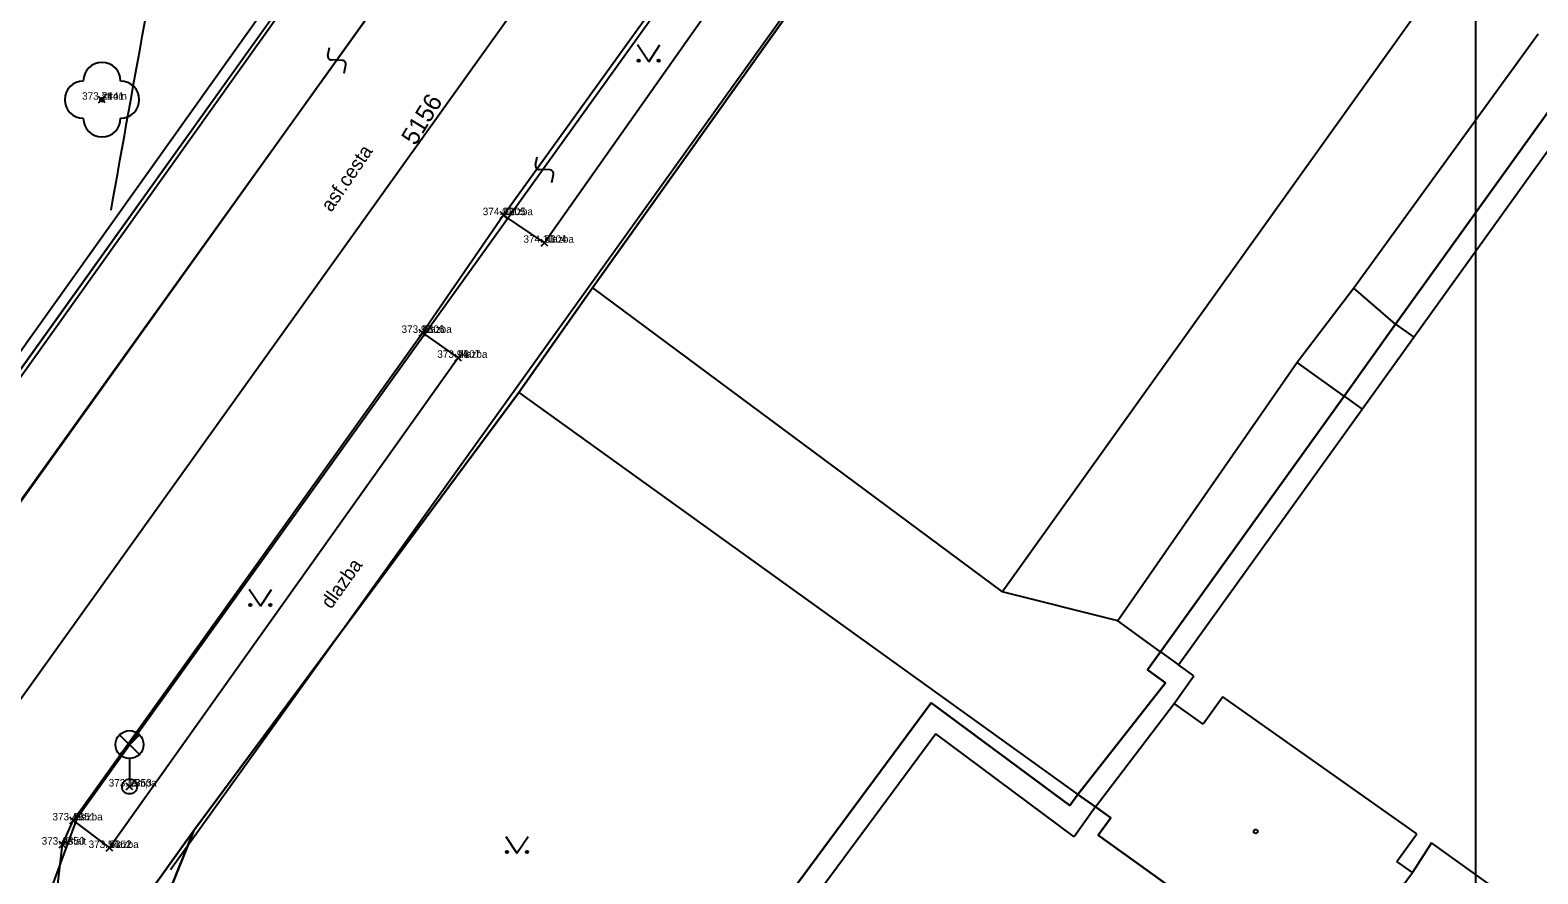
# Model space of a CAD drawing. Extents: x -400488 to -400124, y -1251493 to -1251223.
# Drawn here: x -400289.23 to -400248.76, y -1251399.85 to -1251377.2 of the extents above; entities that cross this region are included whole.
import ezdxf

# ---------------------------------------------------------------- set-up
doc = ezdxf.new("R2010")
doc.units = 0
for name, color, linetype in [('Level 20', 7, 'Continuous'), ('Level 21', 7, 'Continuous'), ('Level 22', 7, 'Continuous'), ('Level 23', 7, 'Continuous'), ('Level 3', 7, 'Continuous'), ('Level 31', 7, 'Continuous'), ('Level 32', 7, 'Continuous'), ('Level 35', 7, 'Continuous'), ('Level 36', 7, 'Continuous'), ('Level 49', 7, 'Continuous'), ('Level 53', 7, 'Continuous'), ('Level 63', 7, 'Continuous')]:
    doc.layers.add(name, color=color, linetype=linetype)

msp = doc.modelspace()

# ---------------------------------------------------------------- linework, layer by layer
at = {"layer": 'Level 20'}
for p, q in [((-400287.388, -1251379.158), (-400287.212, -1251378.982)), ((-400287.212, -1251379.158), (-400287.388, -1251378.982)), ((-400276.608, -1251382.258), (-400276.432, -1251382.082)), ((-400276.432, -1251382.258), (-400276.608, -1251382.082)), ((-400275.508, -1251382.998), (-400275.332, -1251382.822)), ((-400275.332, -1251382.998), (-400275.508, -1251382.822)), ((-400278.788, -1251385.418), (-400278.612, -1251385.242)), ((-400278.612, -1251385.418), (-400278.788, -1251385.242)), ((-400277.828, -1251386.088), (-400277.652, -1251385.912)), ((-400277.652, -1251386.088), (-400277.828, -1251385.912)), ((-400286.648, -1251397.598), (-400286.472, -1251397.422)), ((-400286.472, -1251397.598), (-400286.648, -1251397.422)), ((-400288.158, -1251398.508), (-400287.982, -1251398.332)), ((-400287.982, -1251398.508), (-400288.158, -1251398.332)), ((-400288.448, -1251399.158), (-400288.272, -1251398.982)), ((-400288.272, -1251399.158), (-400288.448, -1251398.982)), ((-400287.188, -1251399.248), (-400287.012, -1251399.072)), ((-400287.012, -1251399.248), (-400287.188, -1251399.072))]:
    msp.add_line(p, q, dxfattribs=at)
at = {"layer": 'Level 3'}
msp.add_lwpolyline([(-400397.431, -1251233.087), (-400250.431, -1251233.087), (-400250.431, -1251440.987), (-400397.431, -1251440.987)], close=True, dxfattribs=at)
at = {"layer": 'Level 31'}
for points in [[(-400252.627, -1251354.111), (-400255.45, -1251357.92), (-400285.456, -1251399.746)], [(-400256.77, -1251357.04), (-400270.17, -1251375.46), (-400275.42, -1251382.91), (-400276.52, -1251382.17), (-400278.7, -1251385.33), (-400277.74, -1251386), (-400287.1, -1251399.16)], [(-400288.07, -1251398.42), (-400287.1, -1251399.16)]]:
    msp.add_lwpolyline(points, dxfattribs=at)
at = {"layer": 'Level 32'}
msp.add_line((-400290.55, -1251396.645), (-400264.548, -1251360.319), dxfattribs=at)
for points in [[(-400270.68, -1251354.37), (-400269.393, -1251355.452), (-400268.89, -1251355.918), (-400268.52, -1251356.37), (-400268.265, -1251356.83), (-400268.08, -1251357.34), (-400267.96, -1251358.23), (-400267.913, -1251358.721), (-400267.9, -1251359.2), (-400268.092, -1251359.586), (-400270.52, -1251363.46), (-400278.03, -1251373.86), (-400293.48, -1251395.44), (-400293.769, -1251395.863), (-400294.17, -1251396.23), (-400294.49, -1251396.36), (-400295.676, -1251396.619), (-400296.86, -1251396.78), (-400297.255, -1251396.759), (-400297.65, -1251396.69), (-400298.36, -1251396.445), (-400298.94, -1251396.17), (-400299.54, -1251395.8), (-400299.67, -1251395.66)], [(-400276.52, -1251382.17), (-400257.84, -1251356.24)], [(-400288.07, -1251398.42), (-400278.7, -1251385.33)], [(-400287.23, -1251403.87), (-400287.71, -1251403.463), (-400288.16, -1251402.92), (-400288.414, -1251402.215), (-400288.52, -1251401.51), (-400288.49, -1251400.213), (-400288.36, -1251399.07), (-400288.07, -1251398.42)]]:
    msp.add_lwpolyline(points, dxfattribs=at)
at = {"layer": 'Level 35'}
for points in [[(-400289.76, -1251340.83), (-400270.68, -1251354.37), (-400270.2, -1251355.011), (-400269.86, -1251355.62), (-400269.639, -1251356.125), (-400269.5, -1251356.63), (-400269.449, -1251357.125), (-400269.44, -1251357.66), (-400269.496, -1251358.046), (-400269.6, -1251358.5), (-400269.799, -1251358.893), (-400270.05, -1251359.32), (-400279.37, -1251372.32), (-400292.97, -1251391.4)], [(-400271.73, -1251354.05), (-400270.963, -1251354.66), (-400270.536, -1251355.23), (-400270.219, -1251355.798), (-400270.017, -1251356.259), (-400269.894, -1251356.704), (-400269.849, -1251357.149), (-400269.84, -1251357.634), (-400269.89, -1251357.973), (-400269.979, -1251358.363), (-400270.151, -1251358.701), (-400270.386, -1251359.102), (-400279.695, -1251372.087), (-400293.283, -1251391.15)]]:
    msp.add_lwpolyline(points, dxfattribs=at)
at = {"layer": 'Level 36'}
for p, q in [((-400272.625, -1251378.051), (-400272.925, -1251377.601)), ((-400272.625, -1251378.051), (-400272.325, -1251377.601)), ((-400283.047, -1251392.669), (-400283.347, -1251392.219)), ((-400283.047, -1251392.669), (-400282.747, -1251392.219))]:
    msp.add_line(p, q, dxfattribs=at)
for centre, radius in [((-400272.895, -1251378.021), 0.03), ((-400272.355, -1251378.021), 0.03), ((-400287.3, -1251379.07), 0.05), ((-400283.317, -1251392.639), 0.03), ((-400282.777, -1251392.639), 0.03)]:
    msp.add_circle(centre, radius, dxfattribs=at)
for centre, start, end in [((-400287.3, -1251378.57), 0, 180), ((-400287.8, -1251379.07), 90, 270), ((-400286.8, -1251379.07), 270, 90), ((-400287.3, -1251379.57), 180, 0)]:
    msp.add_arc(centre, 0.5, start, end, dxfattribs=at)
at = {"layer": 'Level 49'}
for points in [[(-400287.056, -1251382.036), (-400285.095, -1251371.378), (-400283.83, -1251364.736), (-400283.748, -1251364.223), (-400283.689, -1251363.872), (-400283.457, -1251363.276), (-400283.446, -1251363.218), (-400283.447, -1251363.211), (-400283.984, -1251359.342), (-400286.608, -1251354.299), (-400287.35, -1251353.443), (-400287.372, -1251353.421), (-400290.829, -1251350.218), (-400294.574, -1251347.519), (-400294.601, -1251347.503), (-400295.474, -1251347.083), (-400295.494, -1251347.073), (-400299.293, -1251344.638), (-400304.542, -1251340.608), (-400305.224, -1251339.982), (-400305.246, -1251339.958), (-400308.629, -1251336.24), (-400309.532, -1251335.395)], [(-400298.594, -1251390.918), (-400297.579, -1251389.803), (-400296.576, -1251388.675), (-400295.294, -1251386.973), (-400294.717, -1251386.031), (-400294.176, -1251385.068), (-400293.64, -1251384.103), (-400293.079, -1251383.154), (-400292.558, -1251382.354), (-400292.017, -1251381.567), (-400291.474, -1251380.779), (-400290.946, -1251379.978), (-400290.936, -1251379.958), (-400290.353, -1251377.108), (-400290.345, -1251377.073), (-400289.148, -1251371.673), (-400289.131, -1251371.633), (-400288.68, -1251369.757), (-400288.682, -1251369.751), (-400289.179, -1251365.184), (-400289.187, -1251365.045), (-400289.199, -1251364.086), (-400289.178, -1251363.127), (-400289.151, -1251362.167), (-400289.146, -1251361.208), (-400289.326, -1251359.947), (-400289.998, -1251358.61), (-400290.194, -1251358.383), (-400290.2, -1251358.378), (-400291.608, -1251356.855), (-400292.307, -1251356.088), (-400293.021, -1251355.336), (-400293.116, -1251355.24), (-400296.365, -1251351.788), (-400297.616, -1251350.178), (-400299.549, -1251347.891), (-400299.559, -1251347.877), (-400299.595, -1251347.847), (-400301.142, -1251346.859), (-400302.556, -1251345.879), (-400307.962, -1251342.189), (-400307.971, -1251342.179), (-400307.982, -1251342.152), (-400308.883, -1251340.471), (-400309.528, -1251339.56), (-400310.26, -1251338.706), (-400310.968, -1251337.837), (-400311.406, -1251337.164)]]:
    msp.add_spline(points, degree=3, dxfattribs=at)
at = {"layer": 'Level 53'}
for p, q in [((-400286.825, -1251396.65), (-400286.295, -1251396.12)), ((-400286.295, -1251396.12), (-400286.825, -1251396.65)), ((-400286.295, -1251396.65), (-400286.825, -1251396.12)), ((-400286.56, -1251396.76), (-400286.56, -1251397.31))]:
    msp.add_line(p, q, dxfattribs=at)
for centre, radius in [((-400286.56, -1251396.385), 0.375), ((-400286.56, -1251397.51), 0.2)]:
    msp.add_circle(centre, radius, dxfattribs=at)
at = {"layer": 'Level 63'}
for p, q in [((-400244.75, -1251338.16), (-400287.97, -1251398.37)), ((-400274.13, -1251384.12), (-400255.52, -1251358)), ((-400255.52, -1251358), (-400274.13, -1251384.12)), ((-400293.18, -1251391.47), (-400270.09, -1251359.2)), ((-400270.09, -1251359.2), (-400293.18, -1251391.47)), ((-400267.74, -1251359.55), (-400294.25, -1251396.47)), ((-400263.14, -1251392.28), (-400244.43, -1251366.11)), ((-400281.236, -1251377.883), (-400281.188, -1251377.665)), ((-400248.75, -1251377.31), (-400253.7, -1251384.13)), ((-400280.848, -1251378.016), (-400281.142, -1251378.004)), ((-400280.802, -1251378.355), (-400280.754, -1251378.137)), ((-400247.56, -1251378.11), (-400252.58, -1251385.1)), ((-400252.58, -1251385.1), (-400247.56, -1251378.11)), ((-400252.09, -1251385.45), (-400247.07, -1251378.46)), ((-400275.661, -1251380.822), (-400275.614, -1251380.605)), ((-400275.274, -1251380.955), (-400275.567, -1251380.944)), ((-400275.227, -1251381.294), (-400275.18, -1251381.076)), ((-400276.11, -1251386.93), (-400274.13, -1251384.12)), ((-400274.13, -1251384.12), (-400276.11, -1251386.93)), ((-400274.13, -1251384.12), (-400263.14, -1251392.28)), ((-400253.7, -1251384.13), (-400255.22, -1251386.13)), ((-400252.58, -1251385.1), (-400253.7, -1251384.13)), ((-400252.58, -1251385.1), (-400253.96, -1251387.03)), ((-400253.96, -1251387.03), (-400252.58, -1251385.1)), ((-400252.58, -1251385.1), (-400252.09, -1251385.45)), ((-400253.47, -1251387.38), (-400252.09, -1251385.45)), ((-400255.22, -1251386.13), (-400260.03, -1251393.06)), ((-400253.96, -1251387.03), (-400255.22, -1251386.13)), ((-400284.83, -1251398.69), (-400276.11, -1251386.93)), ((-400276.11, -1251386.93), (-400284.83, -1251398.69)), ((-400276.11, -1251386.93), (-400261.11, -1251397.72)), ((-400253.96, -1251387.03), (-400258.89, -1251393.89)), ((-400258.89, -1251393.89), (-400253.96, -1251387.03)), ((-400258.4, -1251394.24), (-400253.47, -1251387.38)), ((-400253.96, -1251387.03), (-400253.47, -1251387.38)), ((-400260.03, -1251393.06), (-400263.14, -1251392.28)), ((-400258.89, -1251393.89), (-400260.03, -1251393.06)), ((-400258.89, -1251393.89), (-400259.24, -1251394.38)), ((-400259.24, -1251394.38), (-400258.89, -1251393.89)), ((-400258.89, -1251393.89), (-400258.4, -1251394.24)), ((-400257.99, -1251394.54), (-400258.4, -1251394.24)), ((-400259.24, -1251394.38), (-400258.75, -1251394.73)), ((-400258.75, -1251394.73), (-400259.24, -1251394.38)), ((-400258.52, -1251395.28), (-400257.99, -1251394.54)), ((-400258.75, -1251394.73), (-400261.11, -1251397.72)), ((-400261.11, -1251397.72), (-400258.75, -1251394.73)), ((-400265.04, -1251395.26), (-400275.39, -1251409.23)), ((-400275.39, -1251409.23), (-400265.04, -1251395.26)), ((-400261.32, -1251398.02), (-400265.04, -1251395.26)), ((-400265.04, -1251395.26), (-400261.32, -1251398.02)), ((-400260.63, -1251398.06), (-400258.52, -1251395.28)), ((-400257.74, -1251395.84), (-400258.52, -1251395.28)), ((-400257.21, -1251395.1), (-400257.74, -1251395.84)), ((-400252.01, -1251398.78), (-400257.21, -1251395.1)), ((-400264.92, -1251396.1), (-400274.55, -1251409.09)), ((-400261.2, -1251398.86), (-400264.92, -1251396.1)), ((-400261.11, -1251397.72), (-400261.32, -1251398.02)), ((-400261.32, -1251398.02), (-400261.11, -1251397.72)), ((-400260.63, -1251398.06), (-400261.11, -1251397.72)), ((-400261.11, -1251397.72), (-400260.63, -1251398.06)), ((-400260.63, -1251398.06), (-400261.2, -1251398.86)), ((-400260.22, -1251398.35), (-400260.63, -1251398.06)), ((-400260.63, -1251398.06), (-400260.22, -1251398.35)), ((-400287.97, -1251398.37), (-400288.97, -1251401.06)), ((-400288.01, -1251403.12), (-400284.83, -1251398.69)), ((-400284.83, -1251398.69), (-400288.01, -1251403.12)), ((-400284.83, -1251398.69), (-400285.52, -1251400.41)), ((-400285.52, -1251400.41), (-400284.83, -1251398.69)), ((-400260.56, -1251398.82), (-400260.22, -1251398.35)), ((-400260.22, -1251398.35), (-400260.56, -1251398.82)), ((-400276.46, -1251398.85), (-400276.16, -1251399.3)), ((-400276.16, -1251399.3), (-400275.86, -1251398.85)), ((-400254.96, -1251402.83), (-400260.56, -1251398.82)), ((-400260.56, -1251398.82), (-400254.96, -1251402.83)), ((-400252.54, -1251399.52), (-400252.01, -1251398.78)), ((-400251.61, -1251399.02), (-400252.12, -1251399.82)), ((-400248.24, -1251401.44), (-400251.61, -1251399.02)), ((-400252.12, -1251399.82), (-400252.54, -1251399.52)), ((-400254.22, -1251402.65), (-400252.12, -1251399.82))]:
    msp.add_line(p, q, dxfattribs=at)
for centre, radius in [((-400256.33, -1251398.716), 0.054), ((-400276.43, -1251399.27), 0.03), ((-400275.89, -1251399.27), 0.03)]:
    msp.add_circle(centre, radius, dxfattribs=at)
for centre, start, end in [((-400281.138, -1251377.904), 167.7527, 267.7631), ((-400280.852, -1251378.116), 347.753, 87.7631), ((-400275.563, -1251380.844), 167.7527, 267.7631), ((-400275.277, -1251381.055), 347.753, 87.7631)]:
    msp.add_arc(centre, 0.1, start, end, dxfattribs=at)

# ---------------------------------------------------------------- texts
at = {"layer": 'Level 21'}
for s, p in [('2441', (-400287.3, -1251379.07)), ('2305', (-400276.52, -1251382.17)), ('2304', (-400275.42, -1251382.91)), ('2306', (-400278.7, -1251385.33)), ('2307', (-400277.74, -1251386)), ('2353', (-400286.56, -1251397.51)), ('2351', (-400288.07, -1251398.42)), ('2350', (-400288.36, -1251399.07)), ('2352', (-400287.1, -1251399.16))]:
    msp.add_text(s, height=0.2, dxfattribs=at).set_placement(p)
at = {"layer": 'Level 22'}
for s, p in [('strom', (-400287.3, -1251379.07)), ('dlazba', (-400276.52, -1251382.17)), ('dlazba', (-400275.42, -1251382.91)), ('dlazba', (-400278.7, -1251385.33)), ('dlazba', (-400277.74, -1251386)), ('lampa', (-400286.56, -1251397.51)), ('dlazba', (-400288.07, -1251398.42)), ('asfalt', (-400288.36, -1251399.07)), ('dlazba', (-400287.1, -1251399.16))]:
    msp.add_text(s, height=0.2, dxfattribs=at).set_placement(p)
at = {"layer": 'Level 23'}
for s, p in [('373.71', (-400287.833, -1251379.07)), ('374.02', (-400277.078, -1251382.17)), ('374.10', (-400275.986, -1251382.91)), ('373.92', (-400279.258, -1251385.33)), ('373.94', (-400278.298, -1251386)), ('373.65', (-400287.119, -1251397.51)), ('373.49', (-400288.628, -1251398.42)), ('373.47', (-400288.918, -1251399.07)), ('373.54', (-400287.658, -1251399.16))]:
    msp.add_text(s, height=0.2, dxfattribs=at).set_placement(p)
at = {"layer": 'Level 31'}
msp.add_text('dlazba', height=0.375, rotation=54.566, dxfattribs=at).set_placement((-400281.148, -1251392.764))
at = {"layer": 'Level 32'}
msp.add_text('asf.cesta', height=0.375, rotation=55.8347, dxfattribs=at).set_placement((-400281.143, -1251382.109))
at = {"layer": 'Level 63'}
msp.add_text('5156', height=0.48, rotation=58.5659, dxfattribs=at).set_placement((-400278.886, -1251380.326))

doc.saveas('drawing.dxf')
